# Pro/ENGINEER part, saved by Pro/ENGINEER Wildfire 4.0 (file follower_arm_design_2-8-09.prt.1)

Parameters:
  METRIC = "NO"

Other parameters: PITCH, DRILL_DIAMETER, THREAD_DIAMETER, THREADS_PER_INCH, THREAD_DEPTH, THREAD_LENGTH, DRILL_POINT_ANGLE, DRILL_DEPTH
